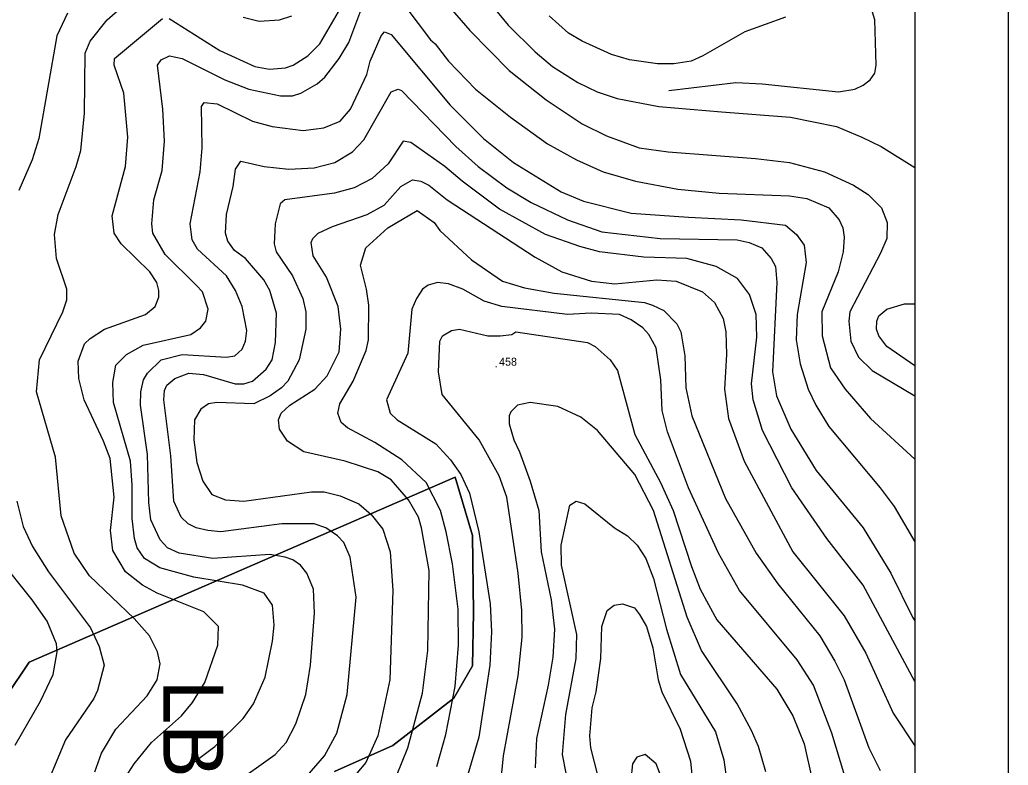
# Model space of a CAD drawing. Extents: x -510989 to -501240, y -1184665 to -1176098.
# Drawn here: x -508760 to -508019, y -1177973 to -1177414 of the extents above; entities that cross this region are included whole.
import ezdxf

# ---------------------------------------------------------------- set-up
doc = ezdxf.new("R2010")
doc.units = 0
for name, color, linetype in [('rozpiska', 7, 'Continuous'), ('STAV_USES', 7, 'Continuous'), ('vrstevnice_01', 7, 'Continuous'), ('vrstevnice_02', 7, 'Continuous'), ('vrstevnice_03', 7, 'Continuous'), ('vrstevnice_05', 7, 'Continuous')]:
    doc.layers.add(name, color=color, linetype=linetype)

msp = doc.modelspace()

# ---------------------------------------------------------------- linework, layer by layer
at = {"layer": 'rozpiska'}
for points in [[(-508019.09, -1176098), (-508019.09, -1184498), (-510989.09, -1184498), (-510989.09, -1176098)], [(-508089.09, -1176168), (-508089.09, -1184428), (-510919.09, -1184428), (-510919.09, -1176168)]]:
    msp.add_lwpolyline(points, close=True, dxfattribs=at)
at = {"layer": 'STAV_USES'}
for p, q in [((-508753.16, -1177895.94), (-508433.91, -1177757.09)), ((-508433.91, -1177757.09), (-508753.16, -1177895.94)), ((-508433.91, -1177757.09), (-508420.88, -1177800.86)), ((-508420.88, -1177800.86), (-508433.91, -1177757.09)), ((-508420.88, -1177800.86), (-508419.95, -1177858.61)), ((-508419.95, -1177858.61), (-508420.88, -1177800.86)), ((-508419.95, -1177858.61), (-508420.88, -1177898.65)), ((-508420.88, -1177898.65), (-508419.95, -1177858.61)), ((-508770.08, -1177920.71), (-508753.16, -1177895.94)), ((-508753.16, -1177895.94), (-508770.08, -1177920.71)), ((-508420.88, -1177898.65), (-508434.84, -1177922.87)), ((-508434.84, -1177922.87), (-508420.88, -1177898.65)), ((-508434.84, -1177922.87), (-508480.46, -1177958.26)), ((-508480.46, -1177958.26), (-508434.84, -1177922.87)), ((-508480.46, -1177958.26), (-508524.21, -1177977.82)), ((-508524.21, -1177977.82), (-508480.46, -1177958.26))]:
    msp.add_line(p, q, dxfattribs=at)
at = {"layer": 'vrstevnice_01'}
for points in [[(-508470.19, -1177367), (-508422.91, -1177422), (-508393.31, -1177452), (-508365.5, -1177474), (-508338.5, -1177492), (-508320.41, -1177501), (-508295.91, -1177510), (-508274.19, -1177513), (-508208.5, -1177518), (-508183.19, -1177521), (-508156.81, -1177528), (-508135.09, -1177538), (-508124, -1177545), (-508114.09, -1177555), (-508109.81, -1177566), (-508110, -1177578), (-508114.91, -1177589), (-508137.91, -1177633), (-508138.5, -1177640), (-508137, -1177655), (-508131.41, -1177667), (-508121.19, -1177677), (-508089.09, -1177695.99)], [(-508648.19, -1177413), (-508610.31, -1177437), (-508584.09, -1177449), (-508573.09, -1177451), (-508561.09, -1177450), (-508555.19, -1177448), (-508544.41, -1177441), (-508535.41, -1177432), (-508521.19, -1177408)], [(-508724.5, -1177409), (-508732.41, -1177426), (-508746.09, -1177503), (-508751, -1177519), (-508760.91, -1177542)], [(-508630.69, -1177926), (-508621.41, -1177911), (-508611.81, -1177883), (-508611.19, -1177869), (-508622.19, -1177858), (-508657.31, -1177844), (-508668.31, -1177838), (-508680.91, -1177828), (-508690.59, -1177812), (-508692.31, -1177797), (-508689.59, -1177772), (-508692.59, -1177743), (-508697.41, -1177730), (-508712.09, -1177699), (-508716, -1177683), (-508716.59, -1177670), (-508711.81, -1177657), (-508707.59, -1177653), (-508696.69, -1177646), (-508665.91, -1177635), (-508658.69, -1177629), (-508656.09, -1177622), (-508655.91, -1177617), (-508657.5, -1177611), (-508662.81, -1177603), (-508684.19, -1177582), (-508689.5, -1177574), (-508690.91, -1177561), (-508681.09, -1177524), (-508679.31, -1177502), (-508682.31, -1177469), (-508689.41, -1177448), (-508689.31, -1177443), (-508653.31, -1177413)], [(-508186.09, -1177412), (-508216.69, -1177423), (-508248.09, -1177441), (-508256.91, -1177445), (-508269.91, -1177447), (-508282.09, -1177447), (-508303.09, -1177444), (-508316.5, -1177440), (-508338.5, -1177430), (-508348.81, -1177424), (-508363.41, -1177411)], [(-508549.69, -1177823), (-508555.5, -1177819), (-508561.41, -1177817), (-508572.69, -1177815), (-508615.41, -1177818), (-508640.81, -1177814), (-508649.41, -1177810), (-508655, -1177804), (-508662.09, -1177789), (-508663.59, -1177776), (-508664.5, -1177740), (-508669.81, -1177703), (-508669.59, -1177693), (-508667.59, -1177684), (-508664.59, -1177679), (-508654.19, -1177669), (-508638.59, -1177665), (-508605.31, -1177667), (-508599, -1177666), (-508593.59, -1177661), (-508591.09, -1177655), (-508590.09, -1177647), (-508593.5, -1177629), (-508598.5, -1177617), (-508605.41, -1177606), (-508627, -1177586), (-508631, -1177579), (-508632.59, -1177567), (-508625.09, -1177528), (-508623.59, -1177510), (-508624, -1177479), (-508621.91, -1177476), (-508612.31, -1177477), (-508585.81, -1177490), (-508571.09, -1177494), (-508547.91, -1177497), (-508532.31, -1177495), (-508520, -1177490), (-508512.31, -1177481), (-508500.09, -1177455), (-508497.5, -1177445), (-508489.41, -1177426), (-508486.69, -1177423), (-508481.69, -1177425), (-508437.59, -1177478), (-508412.5, -1177503), (-508390.09, -1177521), (-508354.31, -1177543), (-508337.69, -1177550), (-508301.81, -1177559), (-508258.81, -1177562), (-508219.31, -1177564), (-508186.19, -1177568), (-508177.81, -1177575), (-508172.19, -1177583), (-508170.69, -1177596), (-508177.41, -1177635), (-508178, -1177654), (-508175.09, -1177672), (-508169, -1177691), (-508163.41, -1177703), (-508153.59, -1177719), (-508115, -1177765), (-508104.5, -1177779), (-508089.09, -1177805.54)], [(-508089.09, -1177910.32), (-508127.91, -1177838), (-508155.19, -1177803), (-508181.41, -1177765), (-508203.31, -1177722), (-508210.31, -1177699), (-508211.59, -1177687), (-508207.5, -1177652), (-508208, -1177635), (-508213.09, -1177620), (-508222, -1177608), (-508238.09, -1177599), (-508260, -1177593), (-508292.41, -1177592), (-508325.5, -1177588), (-508340.41, -1177584), (-508366.19, -1177575), (-508400.59, -1177556), (-508428.5, -1177535), (-508441.59, -1177524), (-508467, -1177506), (-508472.69, -1177505), (-508484, -1177522), (-508496.09, -1177533), (-508509.5, -1177540), (-508524.41, -1177544), (-508561.5, -1177549), (-508565.09, -1177552), (-508568.91, -1177567), (-508569.59, -1177582), (-508568.09, -1177588), (-508555.81, -1177606), (-508548.09, -1177623), (-508545.69, -1177633), (-508545.69, -1177646), (-508550.81, -1177669), (-508559.19, -1177685), (-508564, -1177690), (-508572.59, -1177696), (-508584.91, -1177702), (-508612.59, -1177701), (-508618.81, -1177702), (-508624.41, -1177706), (-508629.31, -1177714), (-508629.69, -1177729), (-508627.59, -1177746), (-508623.09, -1177760), (-508616.19, -1177770), (-508606.09, -1177774), (-508592.19, -1177775), (-508541.59, -1177768), (-508532.09, -1177768), (-508520.09, -1177771), (-508506, -1177777), (-508496.91, -1177785), (-508488, -1177796), (-508482.59, -1177813), (-508480.5, -1177842)], [(-508521.91, -1177709), (-508520.41, -1177702), (-508510.31, -1177685), (-508500.5, -1177662), (-508498.69, -1177654), (-508498.59, -1177628), (-508500.31, -1177616), (-508504.91, -1177598), (-508500.81, -1177585), (-508484.19, -1177570), (-508462.41, -1177557), (-508449.59, -1177566), (-508445.19, -1177572), (-508421.59, -1177594), (-508398.41, -1177610), (-508381.81, -1177615), (-508359.5, -1177619), (-508291.91, -1177626), (-508285.91, -1177628), (-508277.41, -1177632), (-508267.59, -1177642), (-508264.5, -1177648), (-508261.69, -1177666), (-508260.81, -1177690), (-508256.41, -1177711), (-508231.09, -1177773), (-508208.19, -1177814), (-508191.91, -1177837), (-508160.31, -1177876), (-508149.19, -1177895), (-508142, -1177909), (-508123.59, -1177960), (-508115, -1177977)], [(-508403.31, -1178024), (-508397.5, -1177966), (-508386.5, -1177906), (-508383.59, -1177877), (-508383.81, -1177857), (-508386.59, -1177829), (-508395.09, -1177772), (-508400.81, -1177756), (-508415.81, -1177729), (-508443.59, -1177695), (-508446.31, -1177678), (-508445.41, -1177655), (-508443.31, -1177651), (-508436.69, -1177647), (-508430.5, -1177646), (-508409.31, -1177651), (-508400.19, -1177651), (-508391.31, -1177650), (-508388.31, -1177648), (-508334.69, -1177656), (-508328.81, -1177659), (-508317.69, -1177669), (-508312, -1177677), (-508299, -1177725), (-508279.91, -1177761), (-508270.41, -1177782), (-508256.59, -1177824), (-508250.09, -1177841), (-508237.69, -1177864), (-508192.5, -1177916), (-508180.5, -1177936), (-508172.09, -1177957), (-508159.69, -1178013)], [(-508447.59, -1177974), (-508440.81, -1177950), (-508433.81, -1177914), (-508431.31, -1177883), (-508431.69, -1177856), (-508435.81, -1177822), (-508440.59, -1177798), (-508444.91, -1177782), (-508455.59, -1177761), (-508473.69, -1177744), (-508494, -1177731), (-508514.5, -1177720), (-508519.41, -1177716), (-508521.91, -1177709)], [(-508762.59, -1177775), (-508757.69, -1177794), (-508750.81, -1177809), (-508738.69, -1177828), (-508707.31, -1177870), (-508700.69, -1177884), (-508697.09, -1177898), (-508702, -1177917), (-508704.69, -1177923), (-508726.09, -1177954), (-508745.31, -1178000)], [(-508350.59, -1177979), (-508353.31, -1177965), (-508350.81, -1177935), (-508343.09, -1177893), (-508342.5, -1177875), (-508354.09, -1177823), (-508354.41, -1177808), (-508347.91, -1177778), (-508343.09, -1177775), (-508336.69, -1177777), (-508314.31, -1177795), (-508304.59, -1177801), (-508297.31, -1177808), (-508290.91, -1177818), (-508285.19, -1177833), (-508275.31, -1177871), (-508264.81, -1177905), (-508238.69, -1177948), (-508232.31, -1177969), (-508223.41, -1178035)], [(-508601, -1177988), (-508568.69, -1177965), (-508560.59, -1177956), (-508553.31, -1177942), (-508545.91, -1177920), (-508542.41, -1177898), (-508539.41, -1177859), (-508540, -1177841), (-508545.09, -1177829), (-508549.69, -1177823)], [(-508480.5, -1177842), (-508482.91, -1177909), (-508491.69, -1177951), (-508500.91, -1177971), (-508514.31, -1177987)], [(-508692.17, -1178008.94), (-508679, -1177979), (-508674.5, -1177972), (-508661.59, -1177956), (-508639, -1177936), (-508630.69, -1177926)], [(-508278, -1177985), (-508283.09, -1177972), (-508291.41, -1177965), (-508297.59, -1177967), (-508300.91, -1177972), (-508302.09, -1177984)]]:
    msp.add_lwpolyline(points, dxfattribs=at)
at = {"layer": 'vrstevnice_02'}
for points in [[(-508437.5, -1177365), (-508394, -1177418), (-508373.81, -1177438), (-508360.81, -1177449), (-508341.81, -1177461), (-508327.41, -1177468), (-508312.41, -1177473), (-508281.19, -1177479), (-508234, -1177483), (-508182.31, -1177487), (-508147.91, -1177494), (-508128.81, -1177502), (-508114.31, -1177509), (-508089.09, -1177524.69)], [(-508480.81, -1177391), (-508452.41, -1177429), (-508448.81, -1177432), (-508438.81, -1177445), (-508418.59, -1177466), (-508392.41, -1177487), (-508364.59, -1177507), (-508342.81, -1177519), (-508322.91, -1177528), (-508298.5, -1177535), (-508266.91, -1177541), (-508235.81, -1177544), (-508183, -1177546), (-508170.09, -1177548), (-508153.5, -1177555), (-508145.81, -1177564), (-508143, -1177570), (-508142, -1177577), (-508142.91, -1177588), (-508146.69, -1177603), (-508158.81, -1177633), (-508158.69, -1177651), (-508152.31, -1177675), (-508141.31, -1177691), (-508122.41, -1177713), (-508089.09, -1177743.62)], [(-508657.09, -1177888), (-508662.91, -1177876), (-508674.41, -1177863), (-508707.91, -1177831), (-508719.41, -1177814), (-508729.19, -1177786), (-508733.59, -1177742), (-508747.69, -1177693), (-508745.5, -1177669), (-508728.09, -1177633), (-508725.09, -1177624), (-508725.09, -1177616), (-508732.69, -1177593), (-508734.19, -1177575), (-508731.59, -1177560), (-508717.91, -1177524), (-508714.59, -1177512), (-508711.69, -1177484), (-508711.19, -1177439), (-508707.41, -1177430), (-508694.69, -1177414), (-508674.59, -1177396)], [(-508634.09, -1177974), (-508614, -1177959), (-508592.69, -1177938), (-508585.09, -1177927), (-508576.41, -1177907), (-508570.69, -1177880), (-508569.59, -1177868), (-508570.81, -1177853), (-508577, -1177844), (-508593.19, -1177838), (-508629.69, -1177832), (-508655.19, -1177825), (-508666.81, -1177818), (-508672.19, -1177810), (-508674.19, -1177803), (-508676, -1177788), (-508676, -1177763), (-508677.31, -1177745), (-508690, -1177701), (-508690.5, -1177686), (-508688.19, -1177673), (-508680.19, -1177665), (-508667.69, -1177658), (-508632.09, -1177650), (-508624.81, -1177645), (-508620.81, -1177640), (-508619, -1177631), (-508623.31, -1177618), (-508627.91, -1177613), (-508651.19, -1177590), (-508660.59, -1177574), (-508661.31, -1177567), (-508659.81, -1177549), (-508653.41, -1177527), (-508651.69, -1177505), (-508652.91, -1177481), (-508657, -1177448), (-508654.31, -1177444), (-508647.91, -1177441), (-508638.41, -1177443), (-508606.5, -1177459), (-508588.59, -1177466), (-508564.91, -1177471), (-508555.69, -1177471), (-508549.5, -1177469), (-508537.31, -1177462), (-508531.5, -1177457), (-508520.81, -1177443), (-508513.59, -1177431), (-508503.91, -1177405)], [(-508592.81, -1177412), (-508580.91, -1177415), (-508565.5, -1177414), (-508556.19, -1177411)], [(-508577.19, -1177609), (-508591.09, -1177593), (-508599.19, -1177587), (-508604.31, -1177580), (-508606, -1177574), (-508605.41, -1177560), (-508600.19, -1177539), (-508598.5, -1177526), (-508594.5, -1177520), (-508577, -1177524), (-508558.59, -1177526), (-508539.59, -1177525), (-508524, -1177521), (-508510.91, -1177513), (-508502.19, -1177504), (-508481.81, -1177468), (-508476.59, -1177466), (-508474.09, -1177467), (-508433.31, -1177509), (-508416.5, -1177524), (-508395.19, -1177540), (-508376.81, -1177551), (-508349.5, -1177564), (-508323.91, -1177573), (-508280, -1177578), (-508222.31, -1177579), (-508213.31, -1177581), (-508203.81, -1177585), (-508196.81, -1177593), (-508193.5, -1177599), (-508192.69, -1177611), (-508195.81, -1177678), (-508192.81, -1177696), (-508182.19, -1177721), (-508163.19, -1177752), (-508127.91, -1177795), (-508107.09, -1177829), (-508090.81, -1177862), (-508089.09, -1177864.93)], [(-508477.81, -1177981), (-508469.31, -1177960), (-508458.31, -1177919), (-508454.19, -1177887), (-508453.31, -1177827), (-508459, -1177795), (-508461.41, -1177787), (-508468.81, -1177774), (-508481.91, -1177759), (-508491.69, -1177753), (-508516.31, -1177745), (-508547.31, -1177738), (-508559.5, -1177730), (-508565.5, -1177721), (-508566.19, -1177714), (-508564.31, -1177709), (-508557.91, -1177703), (-508539.09, -1177691), (-508529.81, -1177681), (-508520.91, -1177663), (-508519.5, -1177646), (-508521.5, -1177629), (-508530.41, -1177607), (-508540.31, -1177591), (-508541.91, -1177581), (-508540.59, -1177578), (-508536.5, -1177574), (-508525.91, -1177569), (-508499.91, -1177560), (-508487.09, -1177553), (-508474.5, -1177539), (-508465.81, -1177534), (-508459.5, -1177535), (-508453.59, -1177538), (-508439.81, -1177549), (-508373.91, -1177592), (-508353.81, -1177603), (-508331.69, -1177610), (-508314, -1177612), (-508282.59, -1177609), (-508268.09, -1177610), (-508248.41, -1177618), (-508239.31, -1177626), (-508232.91, -1177638), (-508230.81, -1177648), (-508230.41, -1177665), (-508231.91, -1177691), (-508228.81, -1177713), (-508217.09, -1177745), (-508180.69, -1177813)], [(-508544.91, -1177981), (-508531.81, -1177966), (-508522.59, -1177949), (-508514.69, -1177920), (-508508, -1177847), (-508512.5, -1177817), (-508517.41, -1177806), (-508522, -1177801), (-508530.69, -1177795), (-508539.59, -1177792), (-508563.81, -1177792), (-508609.5, -1177798), (-508619.19, -1177797), (-508628.09, -1177795), (-508634, -1177792), (-508639.19, -1177787), (-508644.69, -1177775), (-508647.09, -1177741), (-508652.31, -1177699), (-508651.69, -1177692), (-508649.91, -1177688), (-508644.09, -1177683), (-508633.41, -1177679), (-508622.59, -1177680), (-508598.81, -1177687), (-508592.19, -1177687), (-508585.91, -1177685), (-508575.5, -1177676), (-508571.09, -1177669), (-508568.5, -1177656), (-508567.81, -1177634), (-508572.81, -1177617), (-508577.19, -1177609)], [(-508138.41, -1177992), (-508151.31, -1177949), (-508165, -1177913), (-508177.41, -1177894), (-508220.69, -1177842), (-508236.41, -1177814), (-508258.81, -1177765), (-508274.59, -1177723), (-508278.59, -1177707), (-508279.59, -1177684), (-508283.09, -1177660), (-508288.5, -1177650), (-508293.19, -1177645), (-508301.81, -1177639), (-508310.59, -1177635), (-508331.81, -1177634), (-508349.69, -1177635), (-508398.81, -1177629), (-508412.09, -1177625), (-508428, -1177616), (-508438.81, -1177612), (-508447.09, -1177611), (-508454.09, -1177613), (-508458.31, -1177616), (-508462.81, -1177623), (-508466.31, -1177631), (-508469.31, -1177664), (-508485.31, -1177699), (-508482.5, -1177709), (-508477.19, -1177714), (-508448.19, -1177732), (-508437.41, -1177744), (-508429.5, -1177755), (-508423.19, -1177769), (-508416.19, -1177798), (-508407.5, -1177852), (-508406.69, -1177873), (-508407.81, -1177898), (-508416.09, -1177952), (-508432.69, -1178008)], [(-508200.81, -1177978), (-508206.41, -1177959), (-508211.5, -1177947), (-508222.31, -1177927), (-508249, -1177887), (-508259.91, -1177862), (-508285.19, -1177782), (-508299.09, -1177755), (-508327.19, -1177722), (-508339.59, -1177712), (-508356.81, -1177704), (-508377.59, -1177701), (-508387.19, -1177703), (-508392.19, -1177708), (-508393.41, -1177711), (-508393.41, -1177717), (-508389.81, -1177729), (-508385.5, -1177738), (-508377.59, -1177760), (-508371.09, -1177782), (-508369.31, -1177813), (-508361.81, -1177849), (-508359.31, -1177871), (-508360.5, -1177892), (-508364, -1177913), (-508372.91, -1177953), (-508373.81, -1177975)], [(-508180.69, -1177813), (-508142, -1177861), (-508125.91, -1177889), (-508105.31, -1177934), (-508089.09, -1177958.56)], [(-508763.69, -1177958), (-508744.81, -1177925), (-508735.19, -1177905), (-508732.19, -1177888), (-508732.69, -1177882), (-508739.69, -1177865), (-508751, -1177849), (-508775.91, -1177818)], [(-508319.91, -1177857), (-508314.5, -1177853), (-508308.31, -1177852), (-508299.41, -1177855), (-508295.5, -1177860), (-508290.41, -1177869), (-508285.5, -1177885), (-508281.69, -1177909), (-508278.91, -1177918), (-508265.09, -1177946), (-508257.31, -1177970), (-508252.69, -1178019), (-508248.41, -1178038), (-508228.5, -1178088), (-508215, -1178114), (-508207.5, -1178124), (-508180.69, -1178147), (-508166.81, -1178156), (-508149.59, -1178166), (-508089.09, -1178192.33)], [(-508320.91, -1178004), (-508332.09, -1177960), (-508332.81, -1177951), (-508331.09, -1177930), (-508328.09, -1177918), (-508324.5, -1177893), (-508323.91, -1177869), (-508319.91, -1177857)], [(-508704.09, -1177978), (-508699.09, -1177964), (-508688.19, -1177946), (-508664.81, -1177921), (-508657.31, -1177909), (-508655, -1177897), (-508657.09, -1177888)]]:
    msp.add_lwpolyline(points, dxfattribs=at)
at = {"layer": 'vrstevnice_03'}
for points in [[(-508273.59, -1177467), (-508223.31, -1177461), (-508203.59, -1177462), (-508146.31, -1177468), (-508134.19, -1177466), (-508127.91, -1177463), (-508122.5, -1177459), (-508119.19, -1177454), (-508118, -1177448), (-508119, -1177414), (-508123.31, -1177400), (-508149.41, -1177372), (-508153.31, -1177365)], [(-508089.09, -1177673.63), (-508110.19, -1177659), (-508116.09, -1177651), (-508117.91, -1177646), (-508117.69, -1177640), (-508116.09, -1177636), (-508110.19, -1177631), (-508096.81, -1177627), (-508089.09, -1177627)]]:
    msp.add_lwpolyline(points, dxfattribs=at)

# ---------------------------------------------------------------- texts
at = {"layer": 'STAV_USES'}
msp.add_text('LB', height=45, rotation=270, dxfattribs=at).set_placement((-508652.59, -1177908.89))
at = {"layer": 'vrstevnice_05'}
for s, p in [('458', (-508400.87, -1177673.4)), ('.', (-508404.18, -1177674.65))]:
    msp.add_text(s, height=6, dxfattribs=at).set_placement(p)

doc.saveas('drawing.dxf')
